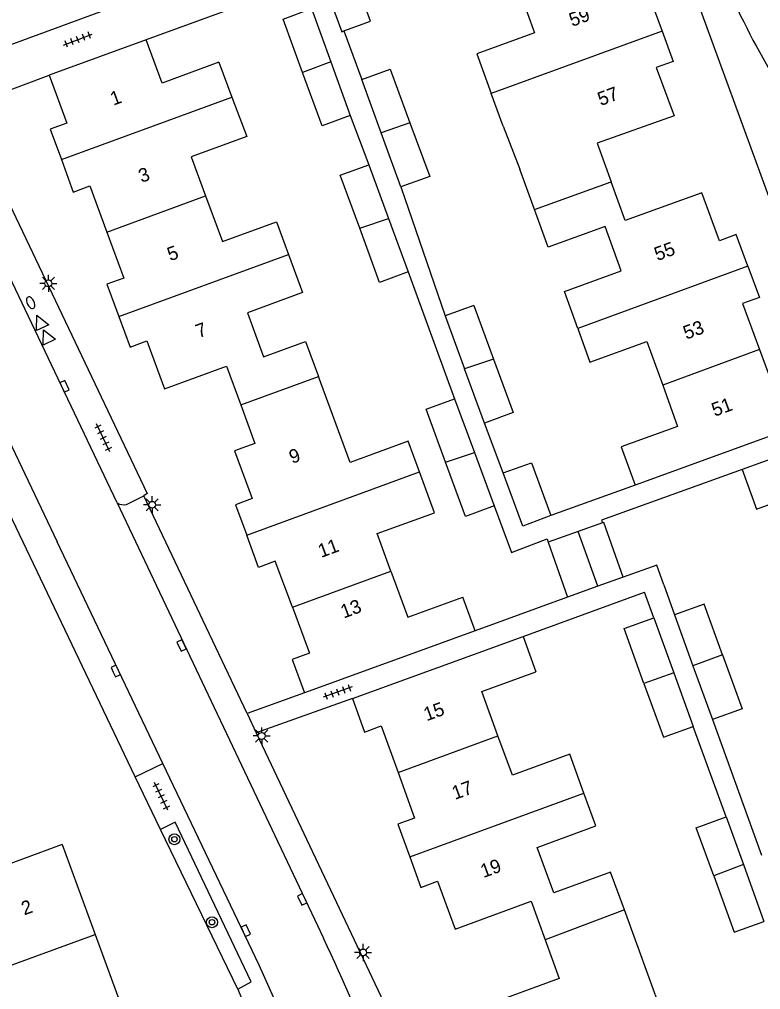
# Model space of a CAD drawing. Extents: x 137999 to 141000, y 397500 to 400501.
# Drawn here: x 138409.2 to 138463.3, y 399967.3 to 400038.2 of the extents above; entities that cross this region are included whole.
import ezdxf

# ---------------------------------------------------------------- set-up
doc = ezdxf.new("R2010")
doc.units = 0
for name, color, linetype in [('gg-afsc-erfafscheiding', 7, 'Continuous'), ('gg-afsc-muur', 7, 'Continuous'), ('gg-anno-huisnummerreeks BGT', 7, 'Continuous'), ('gg-bbg-bijgebouw', 7, 'Continuous'), ('gg-bbg-gedigitaliseerde bebouwing', 7, 'Continuous'), ('gg-bbg-gedigitaliseerde bijgebouw', 7, 'Continuous'), ('gg-bbg-hoofdgebouw', 7, 'Continuous'), ('gg-bbg-tussenscheiding', 7, 'Continuous'), ('gg-knt-verharding', 7, 'Continuous'), ('gg-knt-verharding nz', 7, 'Continuous'), ('gt-grn-weggrens', 7, 'Continuous'), ('gt-symb-boom', 7, 'Continuous'), ('gt-symb-brandkraan', 7, 'Continuous'), ('gt-symb-kolk', 7, 'Continuous'), ('gt-symb-lichtmast', 7, 'Continuous'), ('gt-symb-tegel verharding', 7, 'Continuous'), ('gt-symb-waterafsluiter', 7, 'Continuous')]:
    doc.layers.add(name, color=color, linetype=linetype)

# ---------------------------------------------------------------- blocks, each defined once
blk = doc.blocks.new('gt0-TEG1')
at = {"layer": 'gt-symb-tegel verharding'}
for p, q in [((-1.125, 0), (1.125, 0)), ((-0.9, -0.25), (-0.9, 0.25)), ((-0.45, -0.25), (-0.45, 0.25)), ((0, -0.25), (0, 0.25)), ((0.45, -0.25), (0.45, 0.25)), ((0.9, -0.25), (0.9, 0.25))]:
    blk.add_line(p, q, dxfattribs=at)
blk = doc.blocks.new('gt0-KOLK')
at = {"layer": 'gt-symb-kolk'}
blk.add_lwpolyline([(0, 0), (0.375, 0), (0.375, 0.4), (-0.375, 0.4), (-0.375, 0), (0, 0)], dxfattribs=at)
blk = doc.blocks.new('gt0-LMAST')
at = {"layer": 'gt-symb-lichtmast'}
for p, q in [((-0.182, 0.173), (-0.447, 0.438)), ((-0.005, 0.246), (-0.005, 0.621)), ((0.172, 0.173), (0.437, 0.438)), ((-0.255, -0.004), (-0.63, -0.004)), ((-0.182, -0.181), (-0.447, -0.446)), ((-0.005, -0.254), (-0.005, -0.629)), ((0.437, -0.446), (0.172, -0.181)), ((0.245, -0.004), (0.62, -0.004))]:
    blk.add_line(p, q, dxfattribs=at)
blk.add_circle((-0.005, -0.004), 0.25, dxfattribs=at)
blk = doc.blocks.new('gt0-BOOM')
at = {"layer": 'gt-symb-boom'}
for radius in [0.4, 0.2]:
    blk.add_circle((0, 0), radius, dxfattribs=at)
blk = doc.blocks.new('gt0-WAFSL')
at = {"layer": 'gt-symb-waterafsluiter'}
for p, q in [((-0.5, -0.333), (0, 0.667)), ((0, 0.667), (0.5, -0.333)), ((0.5, -0.333), (-0.5, -0.333))]:
    blk.add_line(p, q, dxfattribs=at)
blk = doc.blocks.new('gt0-BR')
at = {"layer": 'gt-symb-brandkraan'}
for centre, radius, start, end in [((-0.244, 0), 0.206, 107.56694, 252.43307), ((0.599, -2.664), 3, 106.89205, 107.56694), ((0, -0.691), 0.938, 73.10799, 106.89205), ((-0.599, -2.664), 3, 72.43309, 73.10799), ((0.244, 0), 0.206, 287.56695, 72.43309), ((0.599, 2.664), 3, 252.43307, 253.10797), ((0, 0.691), 0.938, 253.10797, 286.89206), ((-0.599, 2.664), 3, 286.89206, 287.56695)]:
    blk.add_arc(centre, radius, start, end, dxfattribs=at)

msp = doc.modelspace()

# ---------------------------------------------------------------- linework, layer by layer
at = {"layer": 'gg-afsc-erfafscheiding'}
for p, q in [((138432.882, 400037.309), (138434.204, 400033.765)), ((138433.357, 400031.133), (138434.704, 400027.536)), ((138437.056, 400025.921), (138440.28, 400016.516)), ((138437.59, 400019.714), (138440.974, 400010.45)), ((138444.509, 400005.036), (138443.153, 400008.677)), ((138454.155, 400004.146), (138448.006, 400001.927)), ((138443.86, 400002.628), (138445.112, 399999.218)), ((138456.256, 399996.856), (138457.02, 399994.667)), ((138449.223, 399995.976), (138442.465, 399993.517)), ((138455.516, 399994.458), (138454.838, 399996.326)), ((138459.789, 399987.035), (138463.384, 399977.129)), ((138460.789, 399979.924), (138458.393, 399986.529)), ((138425.143, 399967.353), (138419.49, 399979.01))]:
    msp.add_line(p, q, dxfattribs=at)
msp.add_lwpolyline([(138445.112, 399999.218), (138447.718, 400000.221), (138447.798, 399999.98)], dxfattribs=at)
at = {"layer": 'gg-afsc-muur'}
for p, q in [((138429.848, 400040.824), (138418.45, 400036.67)), ((138445.972, 399993.088), (138454.838, 399996.326))]:
    msp.add_line(p, q, dxfattribs=at)
for points in [[(138403.717, 400034.542), (138415.133, 400038.724), (138413.839, 400042.111)], [(138461.956, 400005.292), (138451.686, 400001.597), (138451.76, 400001.39)], [(138456.256, 399996.856), (138455.746, 399998.315), (138453.278, 399997.438)]]:
    msp.add_lwpolyline(points, dxfattribs=at)
at = {"layer": 'gg-bbg-bijgebouw'}
for p, q in [((138430.527, 400038.949), (138431.941, 400035.044)), ((138431.941, 400035.044), (138433.357, 400031.133)), ((138448.006, 400001.927), (138445.952, 400001.162)), ((138451.76, 400001.39), (138449.99, 400000.76)), ((138449.99, 400000.76), (138447.798, 399999.98)), ((138447.798, 399999.98), (138449.223, 399995.976)), ((138453.278, 399997.438), (138451.437, 399996.774)), ((138451.437, 399996.774), (138449.223, 399995.976))]:
    msp.add_line(p, q, dxfattribs=at)
for points in [[(138432.882, 400037.309), (138434.83, 400038.02), (138433.401, 400041.932)], [(138431.31, 400041.168), (138432.735, 400037.255), (138432.882, 400037.309)], [(138429.867, 400034.284), (138428.448, 400038.179), (138430.527, 400038.949)], [(138433.357, 400031.133), (138431.29, 400030.38), (138429.867, 400034.284)], [(138453.278, 399997.438), (138451.854, 400001.424), (138451.76, 400001.39)]]:
    msp.add_lwpolyline(points, dxfattribs=at)
at = {"layer": 'gg-bbg-gedigitaliseerde bebouwing'}
for p, q in [((138423.76, 400035.03), (138424.713, 400032.481)), ((138444.51, 400030.353), (138443.646, 400032.741)), ((138444.51, 400030.353), (138445.741, 400027.212)), ((138446.808, 400024.264), (138445.741, 400027.212)), ((138442.465, 399993.517), (138441.572, 399995.978)), ((138445.972, 399993.088), (138446.903, 399990.522)), ((138456.503, 399964.552), (138453.366, 399973.141))]:
    msp.add_line(p, q, dxfattribs=at)
for points in [[(138445.778, 400040.025), (138446.813, 400037.163), (138442.598, 400035.638), (138443.646, 400032.741)], [(138424.713, 400032.481), (138425.791, 400029.599), (138421.744, 400028.113), (138422.786, 400025.273)], [(138422.786, 400025.273), (138424.014, 400021.928), (138427.976, 400023.382), (138428.852, 400020.997)], [(138449.963, 400015.58), (138448.982, 400018.291), (138453.133, 400019.792), (138451.964, 400023.025), (138447.8, 400021.519), (138446.808, 400024.264)], [(138428.852, 400020.997), (138429.877, 400018.203), (138425.84, 400016.721), (138427.017, 400013.515), (138430.091, 400014.643), (138431.028, 400012.091)], [(138449.963, 400015.58), (138450.853, 400013.119), (138455.016, 400014.624), (138456.165, 400011.448)], [(138438.401, 400005.115), (138437.582, 400007.346), (138433.341, 400005.789), (138431.028, 400012.091)], [(138456.165, 400011.448), (138457.255, 400008.433), (138453.142, 400006.945), (138454.155, 400004.146)], [(138436.326, 399997.867), (138435.321, 400000.605), (138439.494, 400002.136), (138438.401, 400005.115)], [(138461.956, 400005.292), (138463.017, 400002.389), (138467.127, 400003.89), (138468.206, 400000.936)], [(138436.326, 399997.867), (138437.559, 399994.506), (138441.572, 399995.978)], [(138444.134, 399985.849), (138442.954, 399989.079), (138446.903, 399990.522)], [(138450.409, 399981.661), (138449.371, 399984.501), (138445.185, 399982.971), (138444.134, 399985.849)], [(138453.366, 399973.141), (138452.362, 399975.889), (138448.218, 399974.371), (138447.003, 399977.698), (138451.285, 399979.262), (138450.409, 399981.661)], [(138412.33, 399977.9), (138403.6, 399974.705), (138406.004, 399968.148)]]:
    msp.add_lwpolyline(points, dxfattribs=at)
at = {"layer": 'gg-bbg-gedigitaliseerde bijgebouw'}
for p, q in [((138434.204, 400033.765), (138436.27, 400034.51)), ((138436.27, 400034.51), (138437.713, 400030.599)), ((138435.608, 400029.877), (138434.204, 400033.765)), ((138437.056, 400025.921), (138435.608, 400029.877)), ((138434.704, 400027.536), (138436.147, 400023.625)), ((138436.147, 400023.625), (138437.59, 400019.714)), ((138442.372, 400017.271), (138440.28, 400016.516)), ((138442.372, 400017.271), (138443.807, 400013.356)), ((138440.28, 400016.516), (138441.703, 400012.634)), ((138443.153, 400008.677), (138441.703, 400012.634)), ((138440.974, 400010.45), (138442.417, 400006.539)), ((138442.417, 400006.539), (138443.86, 400002.628)), ((138445.952, 400001.162), (138444.509, 400005.036)), ((138457.02, 399994.667), (138458.365, 399990.96)), ((138455.516, 399994.458), (138456.969, 399990.452)), ((138458.365, 399990.96), (138459.789, 399987.035)), ((138456.969, 399990.452), (138458.393, 399986.529)), ((138460.789, 399979.924), (138462.051, 399976.446)), ((138462.051, 399976.446), (138463.558, 399972.292))]:
    msp.add_line(p, q, dxfattribs=at)
for points in [[(138437.713, 400030.599), (138439.156, 400026.689), (138437.056, 400025.921)], [(138434.042, 400022.902), (138432.627, 400026.769), (138434.704, 400027.536)], [(138437.59, 400019.714), (138435.49, 400018.946), (138434.042, 400022.902)], [(138443.807, 400013.356), (138445.242, 400009.442), (138443.153, 400008.677)], [(138440.312, 400005.816), (138438.897, 400009.683), (138440.974, 400010.45)], [(138443.86, 400002.628), (138441.76, 400001.86), (138440.312, 400005.816)], [(138444.509, 400005.036), (138446.583, 400005.784), (138448.006, 400001.927)], [(138460.537, 399991.752), (138459.194, 399995.456), (138457.02, 399994.667)], [(138454.794, 399989.668), (138453.342, 399993.669), (138455.516, 399994.458)], [(138460.537, 399991.752), (138461.963, 399987.824), (138459.789, 399987.035)], [(138454.794, 399989.668), (138456.219, 399985.74), (138458.393, 399986.529)], [(138459.89, 399975.624), (138458.616, 399979.135), (138460.789, 399979.924)], [(138459.89, 399975.624), (138461.385, 399971.504), (138463.558, 399972.292)]]:
    msp.add_lwpolyline(points, dxfattribs=at)
at = {"layer": 'gg-bbg-hoofdgebouw'}
for p, q in [((138418.45, 400036.67), (138411.38, 400034.09)), ((138466.58, 400008.67), (138454.155, 400004.146)), ((138467.124, 400007.163), (138461.956, 400005.292)), ((138442.465, 399993.517), (138430.02, 399988.97)), ((138433.52, 399988.57), (138445.972, 399993.088)), ((138412.33, 399977.9), (138414.735, 399971.34)), ((138414.735, 399971.34), (138417.14, 399964.78))]:
    msp.add_line(p, q, dxfattribs=at)
for points in [[(138452.812, 400042.597), (138454.04, 400039.23), (138455.24, 400039.68), (138456.114, 400037.3)], [(138456.114, 400037.3), (138456.93, 400035.08), (138455.69, 400034.63), (138457, 400031.12), (138451.39, 400029.11), (138452.41, 400026.29)], [(138423.76, 400035.03), (138419.62, 400033.49), (138418.45, 400036.67)], [(138411.38, 400034.09), (138412.67, 400030.58), (138411.45, 400030.14), (138412.265, 400027.913)], [(138412.265, 400027.913), (138413.13, 400025.55), (138414.34, 400026.01), (138415.579, 400022.628)], [(138462.375, 400020.14), (138461.52, 400022.44), (138460.31, 400021.99), (138459.03, 400025.5), (138453.43, 400023.47), (138452.41, 400026.29)], [(138415.579, 400022.628), (138416.81, 400019.27), (138415.58, 400018.83), (138416.46, 400016.45)], [(138462.375, 400020.14), (138463.23, 400017.84), (138462, 400017.4), (138463.235, 400014.045)], [(138416.46, 400016.45), (138417.28, 400014.23), (138418.51, 400014.68), (138419.79, 400011.17), (138424.32, 400012.83), (138425.355, 400010.01)], [(138463.235, 400014.045), (138464.47, 400010.69), (138465.67, 400011.13), (138466.58, 400008.67)], [(138425.355, 400010.01), (138426.39, 400007.19), (138424.91, 400006.66), (138426.18, 400003.18), (138424.98, 400002.72), (138425.794, 400000.496)], [(138429.123, 399995.228), (138427.87, 399998.59), (138426.66, 399998.13), (138425.794, 400000.496)], [(138429.123, 399995.228), (138430.37, 399991.88), (138429.12, 399991.42), (138430.02, 399988.97)], [(138433.52, 399988.57), (138434.4, 399986.11), (138435.62, 399986.56), (138436.839, 399983.176)], [(138436.839, 399983.176), (138438.04, 399979.84), (138436.83, 399979.39), (138437.694, 399977.001)], [(138437.694, 399977.001), (138438.5, 399974.77), (138439.73, 399975.22), (138441.01, 399971.73), (138446.55, 399973.76), (138447.58, 399970.94)], [(138447.58, 399970.94), (138448.61, 399968.12), (138443.02, 399966.09), (138444.33, 399962.56), (138443.1, 399962.13), (138443.93, 399959.835)]]:
    msp.add_lwpolyline(points, dxfattribs=at)
at = {"layer": 'gg-bbg-tussenscheiding'}
for p, q in [((138456.114, 400037.3), (138443.646, 400032.741)), ((138431.941, 400035.044), (138429.867, 400034.284)), ((138412.265, 400027.913), (138424.713, 400032.481)), ((138437.713, 400030.599), (138435.608, 400029.877)), ((138446.808, 400024.264), (138452.41, 400026.29)), ((138415.579, 400022.628), (138422.786, 400025.273)), ((138434.042, 400022.902), (138436.147, 400023.625)), ((138416.46, 400016.45), (138428.852, 400020.997)), ((138462.375, 400020.14), (138449.963, 400015.58)), ((138463.235, 400014.045), (138456.165, 400011.448)), ((138443.807, 400013.356), (138441.703, 400012.634)), ((138425.355, 400010.01), (138431.028, 400012.091)), ((138440.312, 400005.816), (138442.417, 400006.539)), ((138425.794, 400000.496), (138438.401, 400005.115)), ((138451.437, 399996.774), (138449.99, 400000.76)), ((138429.123, 399995.228), (138436.326, 399997.867)), ((138460.537, 399991.752), (138458.365, 399990.96)), ((138456.969, 399990.452), (138454.794, 399989.668)), ((138436.839, 399983.176), (138444.134, 399985.849)), ((138437.694, 399977.001), (138450.409, 399981.661)), ((138462.051, 399976.446), (138459.89, 399975.624)), ((138453.366, 399973.141), (138447.58, 399970.94)), ((138406.004, 399968.148), (138414.735, 399971.34))]:
    msp.add_line(p, q, dxfattribs=at)
at = {"layer": 'gg-knt-verharding'}
for p, q in [((138405.08, 400031.73), (138411.38, 400034.09)), ((138407.694, 400008.923), (138411.953, 400000)), ((138417.026, 400002.733), (138418.284, 400003.371)), ((138425.815, 399987.478), (138418.284, 400003.371)), ((138419.673, 399983.825), (138411.953, 400000)), ((138430.02, 399988.97), (138425.815, 399987.478)), ((138433.52, 399988.57), (138426.484, 399986.067)), ((138425.815, 399987.478), (138426.484, 399986.067)), ((138419.49, 399979.01), (138417.65, 399982.859)), ((138425.143, 399967.353), (138426.107, 399967.876))]:
    msp.add_line(p, q, dxfattribs=at)
for points in [[(138416.331, 400002.846), (138399.79, 400037.59), (138399.01, 400039.46), (138389.76, 400064.65)], [(138466.58, 400008.67), (138469.58, 400009.72), (138452.82, 400055.59)], [(138405.08, 400031.73), (138418.53, 400003.53), (138418.284, 400003.371)], [(138417.65, 399982.859), (138405.61, 400008.05), (138405.102, 400008.764), (138404.456, 400009.355)], [(138426.484, 399986.067), (138436.03, 399965.92), (138441.701, 399950.609)], [(138436.599, 399943.775), (138432.01, 399956.33), (138429.31, 399963.27), (138426.7, 399969.1), (138419.673, 399983.825)], [(138426.107, 399967.876), (138420.58, 399979.53), (138419.49, 399979.01)], [(138425.143, 399967.353), (138427.153, 399962.392), (138428.339, 399962.905)]]:
    msp.add_lwpolyline(points, dxfattribs=at)
for centre, radius, start, end in [((138522.214, 400068.163), 67.295, 203.28587, 216.77834), ((138416.818, 400003.645), 0.935, 238.65196, 282.87823)]:
    msp.add_arc(centre, radius, start, end, dxfattribs=at)
at = {"layer": 'gg-knt-verharding nz'}
msp.add_line((138416.331, 400002.846), (138431.398, 399971.077), dxfattribs=at)
msp.add_arc((138286.445, 399902.9), 160.185, 21.4342, 25.18946, dxfattribs=at)
at = {"layer": 'gt-grn-weggrens'}
msp.add_line((138417.65, 399982.859), (138419.673, 399983.825), dxfattribs=at)

# ---------------------------------------------------------------- block references
at = {"layer": 'gt-symb-boom'}
for p in [(138420.515, 399978.291), (138423.26, 399972.231)]:
    msp.add_blockref('gt0-BOOM', p, dxfattribs=at)
at = {"layer": 'gt-symb-brandkraan', "rotation": 115.41160072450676}
msp.add_blockref('gt0-BR', (138410.021, 400017.469), dxfattribs=at)
at = {"layer": 'gt-symb-kolk'}
for p, rotation in [((138412.308, 400011.266), -64.5883992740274), ((138421.216, 399992.523), 115.33527699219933), ((138416.046, 399990.493), -64.46026718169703), ((138430.026, 399973.98), 115.41160072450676), ((138425.543, 399971.522), -64.46026718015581)]:
    msp.add_blockref('gt0-KOLK', p, dxfattribs=dict(at, rotation=rotation))
at = {"layer": 'gt-symb-lichtmast'}
for p in [(138411.318, 400018.885), (138418.895, 400002.714), (138426.892, 399985.837), (138434.291, 399970.027)]:
    msp.add_blockref('gt0-LMAST', p, dxfattribs=at)
at = {"layer": 'gt-symb-tegel verharding'}
for p, rotation in [((138413.461, 400036.681), 20.918204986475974), ((138415.312, 400007.595), 115.28348017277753), ((138432.439, 399989.047), -160.5504312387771), ((138419.544, 399981.42), 115.28348017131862)]:
    msp.add_blockref('gt0-TEG1', p, dxfattribs=dict(at, rotation=rotation))
at = {"layer": 'gt-symb-waterafsluiter'}
for p, rotation in [((138410.747, 400015.943), 25.41160072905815), ((138411.249, 400014.886), 25.411600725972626)]:
    msp.add_blockref('gt0-WAFSL', p, dxfattribs=dict(at, rotation=rotation))

# ---------------------------------------------------------------- texts
at = {"layer": 'gg-anno-huisnummerreeks BGT'}
for s, rotation, p in [('59', 20.1, (138449.549, 400037.603)), ('1', 20.2, (138416.051, 400031.848)), ('57', 20.5, (138451.639, 400031.822)), ('3', 20.1, (138418.113, 400026.209)), ('5', 20.1, (138420.209, 400020.49)), ('55', 20.1, (138455.767, 400020.504)), ('7', 20.1, (138422.284, 400014.872)), ('53', 20.2, (138457.881, 400014.764)), ('51', 20.2, (138459.953, 400009.135)), ('9', 20.1, (138429.108, 400005.69)), ('11', 20.4, (138431.222, 399998.825)), ('13', 20.4, (138432.872, 399994.398)), ('15', 19.8, (138438.923, 399986.901)), ('17', 19.8, (138440.989, 399981.162)), ('19', 20.1, (138443.077, 399975.453)), ('2', 20.1, (138409.553, 399972.726))]:
    msp.add_text(s, height=1, rotation=rotation, dxfattribs=at).set_placement(p)

doc.saveas('drawing.dxf')
